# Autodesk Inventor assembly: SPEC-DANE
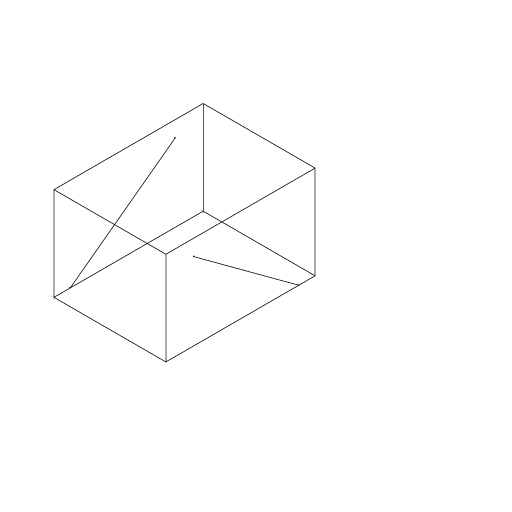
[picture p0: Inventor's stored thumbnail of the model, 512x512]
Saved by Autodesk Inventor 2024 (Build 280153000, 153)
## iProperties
Company: ATC
Created: 2023-03
Part Number: SPEC-DANE
Document SubType Name: Assembly
Designer: Andrzej Jaskulski
Checked By: A.J.
Engr Approved By: Andrzej Jaskulski
Mfg Approved By: Andrzej Jaskulski
Authority: A.J.
Title: A.J.: Kurs R2024-MEP
Author: Andrzej Jaskulski
Revision Number: 1/24
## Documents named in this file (3)
- C:\Users\AndJas\Documents\R2024-MEP\Obszar roboczy\SPEC\SPEC-DANE.iam
- C:\Users\AndJas\Documents\R2024-MEP\Obszar roboczy\SPEC\RAMA-Szkielet.ipt
- C:\Users\AndJas\Documents\R2024-MEP\Obszar roboczy\SPEC\Kotwy.ipt
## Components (2 placed, 2 different names)
1. Kotwy:1
2. RAMA-Szkielet:1
